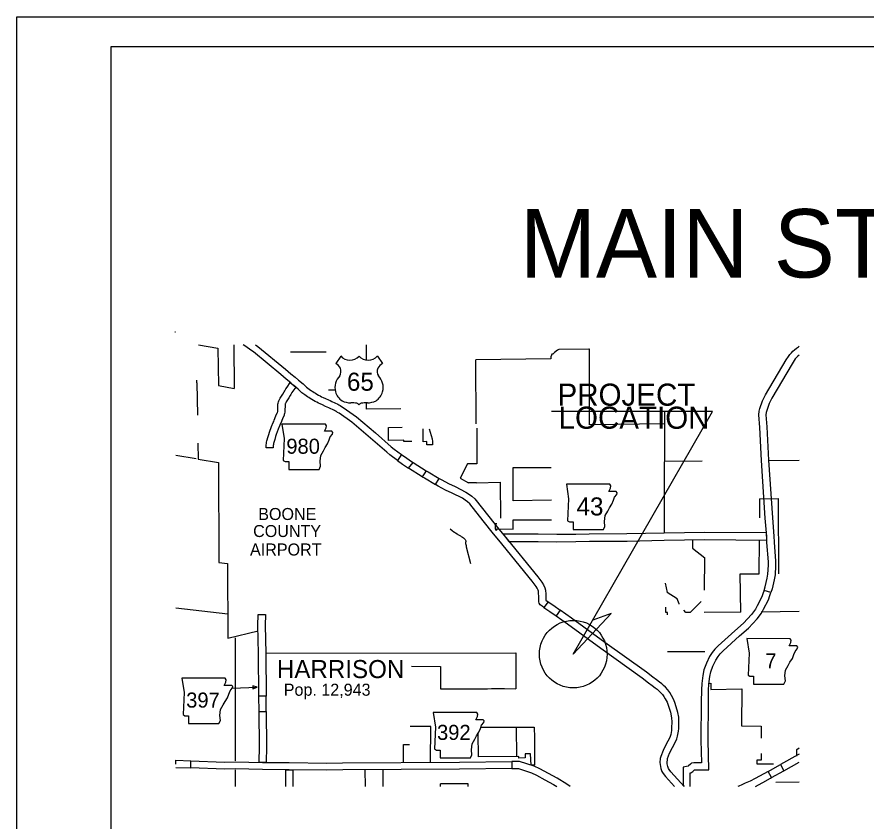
# Model space of a CAD drawing. Extents: x 19118 to 454486, y 1325406 to 1693506.
# Drawn here: x 23760 to 24877, y 1326481 to 1327539 of the extents above; entities that cross this region are included whole.
import ezdxf

# ---------------------------------------------------------------- set-up
doc = ezdxf.new("R2010")
doc.units = 0
for name, color, linetype in [('Default', 7, 'Continuous'), ('S_CURB', 7, 'Continuous'), ('S_EDGE_PAVEMENT', 7, 'Continuous'), ('S_PAVEMENT_CROWN', 7, 'Continuous'), ('S_SHOULDER', 7, 'Continuous')]:
    doc.layers.add(name, color=color, linetype=linetype)

msp = doc.modelspace()

# ---------------------------------------------------------------- linework, layer by layer
at = {"layer": 'Default'}
for p, q in [((24513.2, 1327002.7), (24513.6, 1327102.4)), ((24185.9, 1327093.2), (24179.4, 1327083.2)), ((24234.2, 1327093.2), (24240.7, 1327083.2)), ((24612.2, 1327003.8), (24513.2, 1327002.7)), ((24612.2, 1327003.8), (24611.8, 1326904.7)), ((24613.1, 1326794.5), (24615.8, 1326782.1)), ((24279.1, 1326685.2), (24317.4, 1326684.8)), ((24317.4, 1326684.8), (24317.2, 1326655.1)), ((24304.5, 1326605.7), (24277.3, 1326605.5)), ((24304.1, 1326558.8), (24304.5, 1326605.7)), ((24268.5, 1326558.5), (24268.7, 1326581.9)), ((24268.7, 1326581.9), (24276.4, 1326582))]:
    msp.add_line(p, q, dxfattribs=at)
for points in [[(23968.3, 1327124.7), (23967.6, 1327124.7)], [(23998.7, 1327108.1), (24024.2, 1327103.6)], [(24045.3, 1327108.1), (24045.6, 1327050.5)], [(24134.8, 1327044.9), (24130, 1327049.5), (24124.4, 1327054.2), (24120.1, 1327058), (24114.1, 1327062.6), (24107, 1327068.8), (24070.9, 1327098.5), (24067.6, 1327101.1), (24060.8, 1327105.9), (24057.6, 1327108.1)], [(24073.9, 1327108.1), (24076.8, 1327105.8), (24113, 1327076), (24120.1, 1327069.9), (24126.1, 1327065.2), (24130.5, 1327061.3), (24136.3, 1327056.5), (24140.9, 1327052.1)], [(24219.2, 1327108.1), (24219.5, 1327087.8)], [(24024.2, 1327103.6), (24024.9, 1327054.4)], [(24166.7, 1327098.2), (24119.8, 1327098.4)], [(24473.1, 1327101.9), (24471.2, 1327100.8), (24467.4, 1327097.9), (24465, 1327095.6), (24463.7, 1327095.6)], [(24512.3, 1327102.4), (24473.1, 1327101.9)], [(24513.6, 1327102.4), (24512.3, 1327102.4)], [(24772.3, 1327088.2), (24775.2, 1327092.6), (24777, 1327095.1), (24779.1, 1327097.6), (24781.1, 1327099.6), (24783.3, 1327101.5), (24785.7, 1327103.5), (24788.3, 1327105.4), (24789.3, 1327106.1)], [(24462.6, 1327089.4), (24363.8, 1327088)], [(24364.3, 1327003.9), (24363.8, 1327088)], [(24463.7, 1327095.6), (24463.2, 1327094.4), (24462.7, 1327092.1), (24462.6, 1327089.4)], [(24752.3, 1326781.9), (24743.3, 1326784.6), (24744.7, 1326789.3), (24747.4, 1326800.7), (24748.3, 1326806.2), (24748.8, 1326817.8), (24749, 1326820.9), (24748.8, 1326822.2), (24747, 1326847.8), (24746.7, 1326855.5), (24744.8, 1326879.7), (24739.8, 1326955.5), (24737.7, 1326999.3), (24736.2, 1327015.9), (24736.8, 1327020.8), (24737.7, 1327024.2), (24741.2, 1327034.1), (24745, 1327042.2), (24772.3, 1327088.2)], [(24789.3, 1327094.3), (24787.5, 1327092.8), (24786, 1327091.3), (24784.3, 1327089.3), (24782.9, 1327087.3), (24780.1, 1327083.1)], [(24780.1, 1327083.1), (24753.3, 1327037.8), (24749.9, 1327030.6), (24746.7, 1327021.4), (24746, 1327018.9), (24745.6, 1327015.7), (24747, 1327000), (24749.2, 1326956), (24754.2, 1326880.4), (24756, 1326856), (24756.4, 1326848.4), (24758.1, 1326823.3), (24758.4, 1326821.2), (24758.1, 1326817.3), (24757.7, 1326805.2), (24756.6, 1326798.9), (24753.8, 1326786.9), (24752.3, 1326781.9)], [(23996.7, 1327058), (23996.7, 1327061.3)], [(23996.7, 1327058), (23997.3, 1327015.5)], [(24024.9, 1327054.4), (24045.6, 1327050.5)], [(24097, 1326972.3), (24087.6, 1326972.3), (24087.6, 1326974.2), (24087.8, 1326976.4), (24088, 1326978.2), (24088.4, 1326979.9), (24088.7, 1326981.4), (24089.1, 1326983), (24090, 1326986), (24091.3, 1326990.1), (24092.3, 1326993.2), (24095, 1327000.4), (24097, 1327005.5), (24097.7, 1327007.2), (24098.3, 1327008.6), (24100.7, 1327014.3), (24102.4, 1327018.4), (24102.5, 1327018.8), (24102.7, 1327019.4), (24102.9, 1327020.4), (24103.1, 1327022.2), (24103.2, 1327028.4), (24103.3, 1327029.9), (24103.5, 1327031.3), (24103.9, 1327032.9), (24104.4, 1327034.4), (24105.1, 1327035.8), (24106.1, 1327037.6), (24106.9, 1327039), (24109.6, 1327043.1), (24111.4, 1327046.2), (24112.2, 1327047.5), (24113.8, 1327050.1), (24115.3, 1327052.2), (24119.5, 1327058.5), (24126.6, 1327052.3)], [(24126.6, 1327052.3), (24123, 1327047), (24121.7, 1327045), (24120.2, 1327042.5), (24119.4, 1327041.3), (24117.5, 1327038.2), (24114.9, 1327034.1), (24114.2, 1327033), (24113.5, 1327031.6), (24113.1, 1327030.7), (24112.8, 1327030.1), (24112.7, 1327029.6), (24112.6, 1327029), (24112.6, 1327027.9), (24112.4, 1327021.6), (24112.2, 1327019.2), (24111.9, 1327017.5), (24111.6, 1327016.4), (24111.3, 1327015.4), (24109.4, 1327010.7), (24107, 1327004.9), (24106.4, 1327003.6), (24105.7, 1327002), (24103.7, 1326997), (24101.1, 1326990), (24100.2, 1326987.2), (24099, 1326983.3), (24098.2, 1326980.5), (24097.8, 1326979.2), (24097.5, 1326977.9), (24097.3, 1326976.7), (24097.1, 1326975.5), (24097, 1326973.9), (24097, 1326972.3)], [(24138.6, 1327042.1), (24134.8, 1327044.9)], [(24200.5, 1327006.1), (24183.7, 1327017.8), (24181.8, 1327019), (24180.4, 1327020), (24179, 1327020.8), (24177.9, 1327021.3), (24170.1, 1327025), (24167.9, 1327026), (24166, 1327026.9), (24161.8, 1327028.8), (24158.9, 1327030.1), (24156.5, 1327031.3), (24154.4, 1327032.4), (24152.3, 1327033.5), (24149.9, 1327034.8), (24147.8, 1327036), (24145.9, 1327037.2), (24143.9, 1327038.5), (24142.1, 1327039.7), (24138.6, 1327042.1)], [(24140.9, 1327052.1), (24144.2, 1327049.6)], [(24144.2, 1327049.6), (24147.4, 1327047.4), (24149, 1327046.3), (24150.9, 1327045.1), (24152.5, 1327044.1), (24154.4, 1327043.1), (24156.8, 1327041.8), (24158.7, 1327040.7), (24160.7, 1327039.7), (24163, 1327038.6), (24165.7, 1327037.3), (24169.9, 1327035.4), (24171.9, 1327034.5), (24174.1, 1327033.5), (24182, 1327029.8), (24183.3, 1327029.1), (24185.3, 1327028), (24187, 1327026.9), (24189, 1327025.5), (24206.5, 1327013.3)], [(24178.5, 1327048.1), (24169.7, 1327048.1)], [(24264.9, 1327023.9), (24220, 1327023.1), (24220, 1327031.6)], [(24612.3, 1327020.7), (24612.2, 1327003.8)], [(24206.5, 1327013.3), (24231.5, 1326992.2), (24252.5, 1326973.6), (24256.2, 1326970.6), (24266.1, 1326963.5), (24260.7, 1326955.8)], [(24260.7, 1326955.8), (24250.4, 1326963.2), (24246.4, 1326966.5), (24225.3, 1326985.1), (24200.5, 1327006.1)], [(24279.4, 1326980.9), (24268.8, 1326980.8), (24268.8, 1326982.3), (24248.8, 1326982.2), (24248.7, 1326999.3), (24266.8, 1326999.5)], [(24306.1, 1326984.2), (24306.9, 1326980.8), (24306.8, 1326976.5), (24299.3, 1326976.4), (24299.1, 1326980.5), (24294.3, 1326980.3), (24294.3, 1326997.6)], [(24302.3, 1326997.6), (24306.1, 1326984.2)], [(24364.9, 1326998.3), (24364.9, 1326951.2), (24352.7, 1326951.2), (24343.3, 1326932.4), (24354, 1326926.3)], [(23997.9, 1326978.6), (23998.2, 1326957.4), (24025.2, 1326953), (24025.4, 1326821.5), (24037, 1326820.2), (24037.2, 1326722.1)], [(24266.1, 1326963.5), (24272.8, 1326958.6), (24279.1, 1326954.3), (24281.2, 1326953)], [(23995.6, 1326957.8), (23968.9, 1326962.2)], [(24260.7, 1326955.8), (24267.4, 1326951), (24274, 1326946.4), (24275.3, 1326945.7)], [(24293.3, 1326934.4), (24275.3, 1326945.7), (24281.2, 1326953)], [(24281.2, 1326953), (24298.5, 1326942.2), (24293.3, 1326934.4)], [(24661.8, 1326954.7), (24612, 1326954.3)], [(24789.3, 1326955.6), (24749.4, 1326955.3)], [(24298.5, 1326942.2), (24300.9, 1326940.8), (24315.5, 1326932.1)], [(24463.3, 1326903.5), (24412.8, 1326902.7), (24412.8, 1326946.3), (24463, 1326946.7)], [(24293.3, 1326934.4), (24296.1, 1326932.7), (24310.5, 1326924.1)], [(24373.5, 1326876.4), (24355.8, 1326898.7), (24352.8, 1326901.3), (24349.9, 1326903.5), (24346.1, 1326906), (24332.5, 1326912.9), (24323.8, 1326916.9), (24314.3, 1326921.9), (24310.5, 1326924.1), (24315.5, 1326932.1)], [(24315.5, 1326932.1), (24318.9, 1326930.1), (24327.9, 1326925.3), (24336.6, 1326921.4), (24350.8, 1326914.1), (24355.3, 1326911.2), (24358.7, 1326908.7), (24362.6, 1326905.2), (24380.9, 1326882.2)], [(24364.8, 1326926.5), (24354, 1326926.3)], [(24364.8, 1326926.5), (24395.9, 1326927.1), (24396.4, 1326879.8)], [(24611.8, 1326904.7), (24611.7, 1326860.2)], [(24737.3, 1326905.4), (24737.2, 1326880.3)], [(24737.3, 1326905.4), (24761.8, 1326905.5), (24762.1, 1326806.6)], [(24446.4, 1326780.3), (24446.2, 1326783.6), (24445.8, 1326785), (24444.7, 1326787.6), (24443.1, 1326790), (24438, 1326796.8), (24393.9, 1326851), (24386.9, 1326859.3), (24373.5, 1326876.4)], [(24380.9, 1326882.2), (24394.2, 1326865.2), (24401.2, 1326856.9), (24445.4, 1326802.6), (24450.7, 1326795.5), (24453, 1326792.1), (24454.8, 1326788), (24455.5, 1326785.1), (24455.8, 1326779.7)], [(24390.5, 1326863.8), (24392.4, 1326865.7), (24412.7, 1326865.2), (24412.8, 1326877.8), (24463.5, 1326877.8)], [(24330, 1326865.7), (24332.8, 1326863.7), (24334.9, 1326862), (24335.6, 1326861.4), (24337.1, 1326860.7), (24339.1, 1326859.3), (24340.1, 1326858.4), (24342, 1326857.4), (24343.4, 1326856.8), (24344.5, 1326855.9), (24346.1, 1326855), (24347.5, 1326853.9), (24349, 1326852.7), (24349.9, 1326851.6), (24350.3, 1326851), (24350.6, 1326850.1), (24350.6, 1326849), (24350.3, 1326847.7), (24350.3, 1326846.6), (24350.5, 1326845.4), (24350.9, 1326843.9), (24351.2, 1326842.3)], [(24391.5, 1326872.2), (24389, 1326872.2), (24389, 1326865.8)], [(24389, 1326865.8), (24390.5, 1326863.8)], [(24746.9, 1326851.1), (24746.3, 1326860.5), (24665.3, 1326861), (24611.6, 1326860.2), (24562.7, 1326859.1), (24513.1, 1326858.8), (24495.4, 1326858.4), (24470.3, 1326858.3), (24446, 1326858.7), (24399.8, 1326858.7), (24407.4, 1326849.3)], [(24407.4, 1326849.3), (24445.9, 1326849.3), (24470.2, 1326848.9), (24495.5, 1326849), (24513.3, 1326849.5), (24562.8, 1326849.7), (24611.8, 1326850.8), (24665.4, 1326851.6), (24746.9, 1326851.1)], [(24649, 1326851.4), (24649.1, 1326840.4)], [(24712.4, 1326756.1), (24711.8, 1326806.5), (24736.8, 1326806.7), (24737, 1326851.2)], [(24351.2, 1326842.3), (24356.6, 1326820.2)], [(24649.1, 1326840.4), (24665.4, 1326827.6)], [(24664.8, 1326785.1), (24665.4, 1326827.6)], [(24752.3, 1326781.9), (24743.3, 1326784.6), (24742, 1326781.5), (24740.2, 1326776.2), (24734.3, 1326764.4), (24731.7, 1326759.9), (24726.8, 1326753.2), (24716.1, 1326741.8), (24704.5, 1326731.8), (24682.9, 1326712), (24678.2, 1326707.4), (24674.9, 1326703.1), (24671.4, 1326697.8), (24667.2, 1326688.9), (24664, 1326680.1), (24662.4, 1326672.8), (24661.3, 1326662.1), (24660.9, 1326653.9), (24660.5, 1326637.8), (24660.1, 1326587.7), (24660.8, 1326558.1), (24650.9, 1326558.1), (24647.8, 1326557.3), (24646.2, 1326556.3), (24643.6, 1326554), (24643.1, 1326553.6), (24636.7, 1326552.3), (24636.6, 1326528.4), (24637.9, 1326526.9)], [(24448.4, 1326766), (24447, 1326767.8), (24446.6, 1326769.6), (24446.6, 1326777.6), (24446.4, 1326780.3)], [(24455.8, 1326779.7), (24455.9, 1326778), (24456, 1326771.8)], [(24628.9, 1326773.8), (24615.8, 1326782.1)], [(24631.3, 1326767.1), (24628.9, 1326773.8)], [(24645.9, 1326526.9), (24646, 1326544.6), (24646.8, 1326544.8), (24649.4, 1326546.6), (24651.7, 1326548.6), (24652.1, 1326548.7), (24670.4, 1326548.7), (24669.5, 1326587.8), (24669.9, 1326637.6), (24670.2, 1326653.6), (24670.6, 1326661.4), (24671.7, 1326671.3), (24673, 1326677.5), (24675.9, 1326685.3), (24679.6, 1326693.2), (24682.6, 1326697.7), (24685.3, 1326701.2), (24689.3, 1326705.2), (24710.7, 1326724.8), (24722.6, 1326735), (24734.1, 1326747.2), (24739.6, 1326754.8), (24742.6, 1326760), (24748.8, 1326772.6), (24750.7, 1326778.2), (24752.3, 1326781.9)], [(24459.1, 1326769.8), (24453.1, 1326762.5), (24450.9, 1326764), (24448.4, 1326766)], [(24453.1, 1326762.5), (24461.3, 1326757.1), (24469.3, 1326751.3)], [(24456, 1326771.8), (24459.1, 1326769.8)], [(24459.1, 1326769.8), (24466.6, 1326764.8), (24474.9, 1326758.8)], [(24615.9, 1326752.8), (24616, 1326755.5), (24614, 1326755.5), (24613.7, 1326762.6)], [(24631.6, 1326766.6), (24631.3, 1326767.1)], [(24660.3, 1326770.2), (24645.8, 1326755.6)], [(24037.1, 1326753.4), (23968.9, 1326761.5)], [(24087.7, 1326645.7), (24078.3, 1326645.7), (24077.8, 1326701.9), (24077, 1326738.4), (24077.3, 1326753), (24086.7, 1326753)], [(24086.7, 1326753), (24086.4, 1326738.4), (24087.2, 1326702), (24087.7, 1326645.7)], [(24637.9, 1326526.9), (24620.5, 1326546), (24618.1, 1326549), (24617.3, 1326550.4), (24616.3, 1326553.1), (24615.7, 1326556.7), (24615.5, 1326558.2), (24615.9, 1326562.3), (24616.2, 1326563.6), (24618.9, 1326570.5), (24622.6, 1326578.1), (24626.9, 1326586.3), (24628.2, 1326589.3), (24629.4, 1326593.1), (24630.5, 1326599.4), (24630.8, 1326602.9), (24631.1, 1326612.2), (24630.8, 1326617.8), (24629.8, 1326624.2), (24629, 1326627.2), (24625.9, 1326637.2), (24624, 1326641.8), (24621.4, 1326646.7), (24619.2, 1326650.4), (24616.7, 1326653.8), (24613.3, 1326657.3), (24610.6, 1326659.7), (24608.6, 1326661.8), (24605.4, 1326664.1), (24601.5, 1326667.3), (24596.7, 1326670.7), (24588.3, 1326677.3), (24533.7, 1326716.4), (24489.9, 1326748.2), (24474.9, 1326758.8), (24469.3, 1326751.3)], [(24469.3, 1326751.3), (24484.4, 1326740.6), (24528.2, 1326708.8), (24582.6, 1326669.7), (24591.1, 1326663.1), (24595.8, 1326659.8), (24599.7, 1326656.7), (24602.5, 1326654.7), (24604.1, 1326652.9), (24606.8, 1326650.6), (24609.5, 1326647.8), (24611.4, 1326645.2), (24613.2, 1326642.1), (24615.5, 1326637.8), (24617, 1326634), (24620, 1326624.7), (24620.6, 1326622.2), (24621.5, 1326616.8), (24621.7, 1326612.1), (24621.5, 1326603.6), (24621.2, 1326600.6), (24620.3, 1326595.3), (24619.4, 1326592.5), (24618.5, 1326590.4), (24614.2, 1326582.3), (24610.3, 1326574.2), (24607.2, 1326566.4), (24606.6, 1326563.7), (24606.1, 1326558.2), (24606.3, 1326555.5), (24607.3, 1326550.6), (24608.8, 1326546.4), (24610.4, 1326543.7), (24613.4, 1326540), (24625.3, 1326526.9)], [(24640.4, 1326755.6), (24637.7, 1326759)], [(24645.8, 1326755.6), (24640.4, 1326755.6)], [(24712.4, 1326756.1), (24664.4, 1326755.7)], [(24789.3, 1326756.9), (24739.2, 1326756.3)], [(24037.2, 1326722.1), (24077.2, 1326731.5)], [(24047, 1326722.5), (24047, 1326642.1)], [(24087.2, 1326702), (24416.3, 1326702.8), (24416.6, 1326655.4)], [(24665.3, 1326704), (24615.9, 1326703.8)], [(24670.2, 1326662.5), (24672.9, 1326662.6), (24673.1, 1326654.6), (24713.7, 1326655.2), (24713.5, 1326606.6), (24739.3, 1326606.1), (24739.3, 1326590.4)], [(24043.1, 1326656), (24075.8, 1326657.6)], [(24317.2, 1326655.1), (24372.8, 1326655.4), (24379.2, 1326655.4), (24384.2, 1326655.5), (24388.9, 1326655.6), (24401.5, 1326655.6), (24416.6, 1326655.4)], [(24047, 1326642.1), (24047.1, 1326560.4)], [(24078.5, 1326625.4), (24078.3, 1326645.7)], [(24087.8, 1326625.4), (24087.7, 1326645.7)], [(24087.8, 1326558.5), (24078.4, 1326558.6), (24078.9, 1326579.6), (24078.5, 1326625.4)], [(24078.5, 1326625.4), (24087.8, 1326625.4), (24088.2, 1326579.6), (24087.8, 1326558.5)], [(24367.3, 1326565.7), (24366.8, 1326596.6)], [(24417, 1326604.7), (24440.7, 1326604.9), (24440.8, 1326590.8), (24441, 1326579.3), (24440.9, 1326555), (24436.5, 1326555), (24435.8, 1326569.6), (24428.7, 1326569.6), (24428.5, 1326564.3), (24420.4, 1326564.2), (24420.5, 1326566.2), (24367.3, 1326565.7)], [(24370.3, 1326604.7), (24417, 1326604.7)], [(24417, 1326604.7), (24417.1, 1326566.2)], [(24786.1, 1326566.5), (24786.3, 1326575.4), (24789.3, 1326577.5)], [(23968.9, 1326561.2), (23988.7, 1326560.5)], [(23968.9, 1326556), (23968.9, 1326561.2), (23968.9, 1326561.2)], [(23988.4, 1326551.2), (23988.7, 1326560.5), (24032.9, 1326559), (24047.1, 1326559.2), (24083.1, 1326558.5), (24118.2, 1326558.3)], [(24739.2, 1326570.1), (24739.2, 1326561.6), (24733.5, 1326561.6), (24733.7, 1326556.5), (24755.8, 1326556.7)], [(24789.3, 1326569.1), (24787.7, 1326568.4), (24764.9, 1326555.7)], [(23968.9, 1326551.8), (23988.4, 1326551.2)], [(24118.1, 1326548.9), (24083, 1326549.1), (24047, 1326549.8), (24032.8, 1326549.6), (23988.4, 1326551.2)], [(24411.1, 1326550.4), (24342.1, 1326549.6), (24188.5, 1326548.6), (24167.7, 1326548.3), (24118.1, 1326548.9)], [(24118.2, 1326558.3), (24167.7, 1326557.6), (24188.4, 1326558), (24342.1, 1326559), (24411, 1326559.8), (24411.1, 1326550.4)], [(24488, 1326526.9), (24483.7, 1326529.9), (24470.7, 1326537.8), (24459.2, 1326543.7), (24448, 1326550), (24440.5, 1326553.6), (24421.4, 1326559.8), (24411, 1326559.8), (24411.1, 1326550.4)], [(24411.1, 1326550.4), (24419.9, 1326550.5), (24437, 1326544.9), (24443.7, 1326541.7), (24454.7, 1326535.4), (24466.1, 1326529.6), (24470.6, 1326526.9)], [(24748.4, 1326546.6), (24764.9, 1326555.7)], [(24764.9, 1326555.7), (24769.3, 1326547.4), (24789.3, 1326558.6)], [(24047.1, 1326548.7), (24047.1, 1326526.9)], [(24113.5, 1326526.9), (24113.5, 1326548.9), (24122.8, 1326548.8)], [(24122.8, 1326548.8), (24122.9, 1326526.9)], [(24217.8, 1326548.8), (24218, 1326526.9)], [(24241.3, 1326548.9), (24241.5, 1326526.9)], [(24753, 1326538.4), (24748.4, 1326546.6), (24737.2, 1326540.2), (24731.6, 1326537.2), (24724.8, 1326533.8), (24718.5, 1326531), (24714, 1326529), (24710, 1326527.3), (24708.8, 1326526.9)], [(24731.9, 1326526.9), (24735.9, 1326528.9), (24741.7, 1326532), (24751.8, 1326537.7), (24753, 1326538.4)], [(24753, 1326538.4), (24769.3, 1326547.4)], [(24317.1, 1326526.9), (24317.1, 1326530.1)], [(24353.7, 1326526.9), (24353.7, 1326530.1), (24317.1, 1326530.1)], [(24758.7, 1326532.5), (24789.3, 1326533.1)]]:
    msp.add_lwpolyline(points, dxfattribs=at)
for points in [[(24108.6, 1327003.7), (24111.5, 1326984.6), (24110.2, 1326955.8), (24112.8, 1326954.2), (24117.5, 1326954.2), (24117.5, 1326944), (24157.5, 1326944), (24159.4, 1326948.2), (24158.8, 1326954.8), (24159.7, 1326962.4), (24163.2, 1326968.5), (24165.4, 1326972.9), (24168.6, 1326977.7), (24170.5, 1326982.7), (24172.1, 1326986.9), (24174.9, 1326990.4), (24175.6, 1326992.6), (24174.3, 1326994.2), (24164.5, 1326994.2), (24166.7, 1326998.6), (24167, 1327001.5), (24165.7, 1327003.6)], [(24483, 1326924.4), (24485.8, 1326905.4), (24484.6, 1326876.5), (24487.1, 1326874.9), (24491.9, 1326874.9), (24491.9, 1326864.8), (24531.8, 1326864.8), (24533.7, 1326868.9), (24533.1, 1326875.6), (24534, 1326883.2), (24537.5, 1326889.2), (24539.8, 1326893.6), (24542.9, 1326898.4), (24544.8, 1326903.5), (24546.4, 1326907.6), (24549.3, 1326911.1), (24549.9, 1326913.3), (24548.6, 1326914.9), (24538.8, 1326914.9), (24541, 1326919.3), (24541.3, 1326922.2), (24540, 1326924.4)], [(24720.5, 1326721.3), (24723.4, 1326702.2), (24722.1, 1326673.4), (24724.6, 1326671.8), (24729.4, 1326671.8), (24729.4, 1326661.6), (24769.4, 1326661.6), (24771.3, 1326665.8), (24770.6, 1326672.4), (24771.6, 1326680), (24775.1, 1326686.1), (24777.3, 1326690.5), (24780.5, 1326695.3), (24782.4, 1326700.3), (24784, 1326704.5), (24786.8, 1326708), (24787.5, 1326710.2), (24786.2, 1326711.8), (24776.4, 1326711.8), (24778.6, 1326716.2), (24778.9, 1326719.1), (24777.6, 1326721.2)], [(23976.8, 1326669.3), (23979.6, 1326650.3), (23978.4, 1326621.4), (23980.9, 1326619.8), (23985.7, 1326619.8), (23985.7, 1326609.7), (24025.6, 1326609.7), (24027.5, 1326613.8), (24026.9, 1326620.4), (24027.8, 1326628.1), (24031.3, 1326634.1), (24033.6, 1326638.5), (24036.7, 1326643.3), (24038.6, 1326648.4), (24040.2, 1326652.5), (24043.1, 1326656), (24043.7, 1326658.2), (24042.4, 1326659.8), (24032.6, 1326659.8), (24034.8, 1326664.2), (24035.1, 1326667.1), (24033.8, 1326669.3)], [(24070, 1326659.2), (24070.2, 1326655.4), (24075.8, 1326657.6)], [(24307.8, 1326624.1), (24310.7, 1326605), (24309.4, 1326576.2), (24312, 1326574.6), (24316.7, 1326574.6), (24316.7, 1326564.4), (24356.7, 1326564.4), (24358.6, 1326568.6), (24358, 1326575.2), (24358.9, 1326582.8), (24362.4, 1326588.9), (24364.6, 1326593.3), (24367.8, 1326598.1), (24369.7, 1326603.1), (24371.3, 1326607.3), (24374.1, 1326610.8), (24374.8, 1326613), (24373.5, 1326614.6), (24363.7, 1326614.6), (24365.9, 1326619), (24366.2, 1326621.9), (24364.9, 1326624)]]:
    msp.add_lwpolyline(points, close=True, dxfattribs=at)
for centre, radius, start, end in [((24198, 1327103.4), 15.8, 220.075, 319.6701), ((24222.1, 1327103.4), 15.8, 220.3299, 319.925), ((24171, 1327068.6), 16.9, 30.7809, 59.9883), ((24174.7, 1327073.1), 11.6, 328.8105, 21.2108), ((24245.4, 1327073.1), 11.6, 158.7892, 211.1895), ((24249.2, 1327068.6), 16.9, 120.0117, 149.2191), ((24204.9, 1327049.4), 27, 138.9565, 162.6913), ((24215.2, 1327049.4), 27, 17.3087, 41.0435), ((24196, 1327051.6), 17.8, 160.9576, 197.3819), ((24224.1, 1327051.6), 17.8, 342.6181, 19.0424), ((24198.9, 1327051.6), 20.6, 195.1074, 237.1312), ((24221.2, 1327051.6), 20.6, 302.8688, 344.8926), ((24199.3, 1327058.1), 26.5, 244.0771, 269.5779), ((24199.9, 1326983.1), 48.5, 81.1942, 90.9539), ((24205.9, 1327026.6), 4.65, 28.0342, 72.9864), ((24214.2, 1327026.6), 4.65, 107.0136, 151.9658), ((24220.2, 1326983.1), 48.5, 89.0461, 98.8058), ((24220.8, 1327058.1), 26.5, 270.4221, 295.9229)]:
    msp.add_arc(centre, radius, start, end, dxfattribs=at)
at = {"layer": 'S_EDGE_PAVEMENT'}
msp.add_lwpolyline([(23759.7, 1327539.3), (27093.1, 1327539.3), (27093.1, 1325405.9), (23759.7, 1325405.9)], close=True, dxfattribs=at)
at = {"layer": 'S_PAVEMENT_CROWN'}
for p, q in [((24675.5, 1327020.2), (24463.5, 1327020.2)), ((24492, 1326700.9), (24675.5, 1327020.2)), ((24492, 1326700.9), (24541.7, 1326754.2)), ((24541.7, 1326754.2), (24517.7, 1326745.6))]:
    msp.add_line(p, q, dxfattribs=at)
msp.add_circle((24492, 1326700.9), 44.5, dxfattribs=at)
at = {"layer": 'S_SHOULDER'}
for p, q in [((23883.8, 1327500.3), (27045.6, 1327500.3)), ((23883.8, 1325445.7), (23883.8, 1327500.3))]:
    msp.add_line(p, q, dxfattribs=at)

# ---------------------------------------------------------------- texts
at = {"layer": 'Default'}
for s, height, p in [('65', 23.76, (24194.1, 1327047.5)), ('980', 19.8, (24114.3, 1326964.6)), ('43', 23.76, (24496.4, 1326883.4)), ('BOONE', 15.84, (24077.3, 1326877.4)), ('COUNTY', 15.84, (24070.6, 1326855)), ('AIRPORT', 15.84, (24066.5, 1326830.7)), ('7', 19.8, (24744.8, 1326682.2)), ('HARRISON', 23.76, (24101.9, 1326669.4)), ('Pop. 12,943 ', 15.84, (24110.9, 1326646.2)), ('397', 19.8, (23982.5, 1326630.6)), ('392', 19.8, (24312.7, 1326588.1))]:
    msp.add_text(s, height=height, dxfattribs=at).set_placement(p)
at = {"layer": 'S_CURB'}
for s, height, p in [('MAIN ST.   SPRUCE ST. SIGNAL UPGRADE', 90, (24421.7, 1327196.5)), ('PROJECT', 29.07, (24471.3, 1327027.8)), ('LOCATION', 29.07, (24472.7, 1326997.5))]:
    msp.add_text(s, height=height, dxfattribs=at).set_placement(p)

doc.saveas('drawing.dxf')
